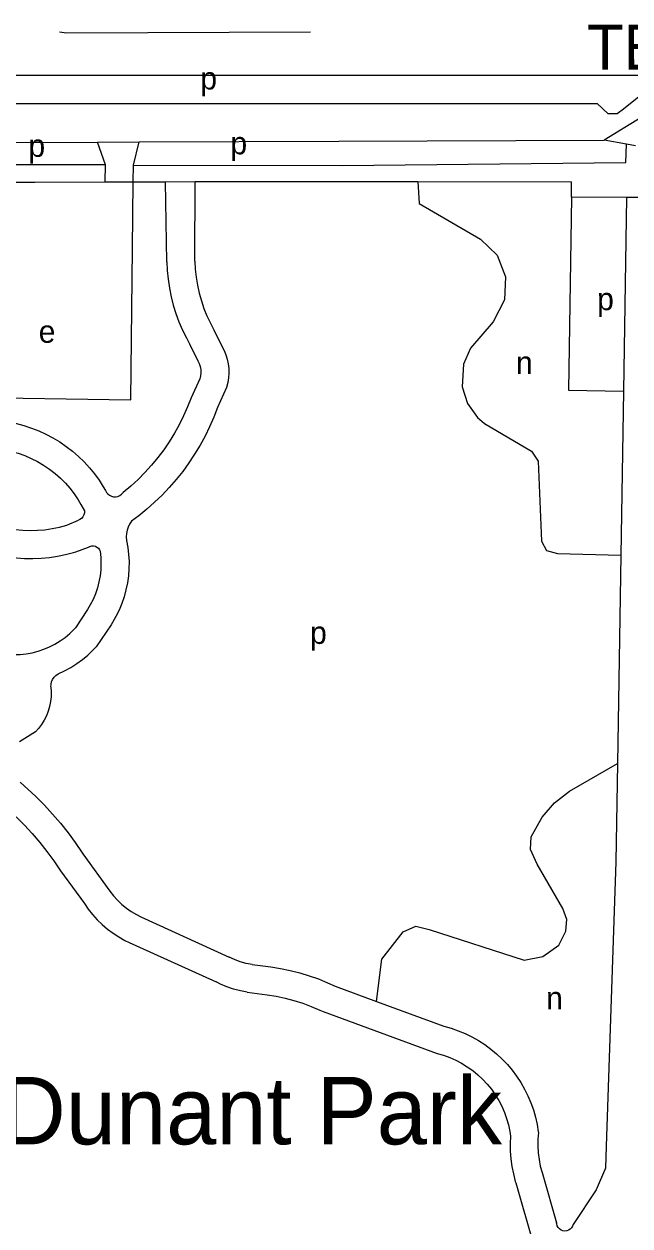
# Model space of a CAD drawing. Extents: x 159675 to 162108, y 386471 to 388472.
# Drawn here: x 160845.9 to 160953.7, y 388134.8 to 388348.5 of the extents above; entities that cross this region are included whole.
import ezdxf

# ---------------------------------------------------------------- set-up
doc = ezdxf.new("R2010")
doc.units = 0
for name, color, linetype in [('BLT_Basislijn', 7, 'Continuous'), ('BLT_Centroide', 7, 'Continuous'), ('BLT_Sport_parknaam', 7, 'Continuous'), ('BLT_Straatnaam_hoofdweg', 7, 'Continuous')]:
    doc.layers.add(name, color=color, linetype=linetype)

msp = doc.modelspace()

# ---------------------------------------------------------------- linework, layer by layer
at = {"layer": 'BLT_Basislijn'}
for p, q in [((160821.1, 388334.42), (160947.87, 388334.42)), ((160955.66, 388331.9), (160949.08, 388327.91)), ((160844.12, 388327.48), (160858.93, 388327.54)), ((160858.93, 388327.54), (160866.37, 388327.57)), ((160865.33, 388323.41), (160866.37, 388327.57)), ((160866.37, 388327.57), (160901.87, 388327.73)), ((160901.87, 388327.73), (160949.08, 388327.91)), ((160953.05, 388327.19), (160949.08, 388327.91)), ((160954.67, 388326.9), (160953.05, 388327.19)), ((160860.38, 388323.49), (160834.93, 388323.49)), ((160865.3, 388320.48), (160865.33, 388323.41)), ((160865.33, 388323.41), (160902.5, 388323.36)), ((160834.87, 388320.46), (160847.78, 388320.42)), ((160847.78, 388320.42), (160860.32, 388320.46)), ((160860.32, 388320.46), (160865.3, 388320.48)), ((160865.17, 388308.55), (160865.3, 388320.48)), ((160865.3, 388320.48), (160871.06, 388320.49)), ((160871.06, 388320.49), (160876.3, 388320.51)), ((160871.28, 388306.27), (160871.06, 388320.49)), ((160876.28, 388306.38), (160876.3, 388320.51)), ((160915.92, 388320.51), (160943.27, 388320.47)), ((160943.27, 388317.73), (160943.27, 388320.47)), ((160953.1, 388317.71), (160943.27, 388317.73)), ((160953.1, 388317.71), (160952.54, 388283.24)), ((160958.1, 388317.71), (160953.1, 388317.71)), ((160879.66, 388294.17), (160881.06, 388291.24)), ((160875.32, 388291.69), (160876.79, 388288.64)), ((160877.15, 388285.46), (160875.62, 388282.07)), ((160881.89, 388283.9), (160880.32, 388280.36)), ((160952.54, 388283.24), (160952.08, 388254.1)), ((160856.01, 388263.13), (160856.63, 388261.97)), ((160853.62, 388259.46), (160855.56, 388260.3)), ((160855.09, 388254.68), (160857.32, 388255.5)), ((160952.08, 388254.1), (160951.48, 388217.02)), ((160857.16, 388244.44), (160855.02, 388241.18)), ((160861.36, 388241.73), (160858.71, 388237.81)), ((160847.89, 388222.68), (160845.07, 388220.88)), ((160951.48, 388217.02), (160951.2, 388199.58)), ((160845.19, 388213.7), (160847.98, 388211.17)), ((160856.34, 388201), (160861.15, 388194.36)), ((160852.34, 388197.98), (160856.61, 388192.15)), ((160951.2, 388199.58), (160949.46, 388149.03)), ((160866.67, 388189.78), (160882.36, 388182.64)), ((160864.57, 388185.24), (160880.04, 388178.21)), ((160886.46, 388181.28), (160889.8, 388180.89)), ((160885.6, 388176.36), (160889.12, 388175.94)), ((160901.26, 388177.43), (160908.59, 388174.74)), ((160908.59, 388174.74), (160920.57, 388170.33)), ((160899.08, 388172.93), (160919.36, 388165.48)), ((160933.36, 388142.49), (160936.55, 388131.55)), ((160938.16, 388143.89), (160940.64, 388135.39)), ((160947.67, 388141.27), (160943.6, 388135.09))]:
    msp.add_line(p, q, dxfattribs=at)
for points in [[(160896.86, 388347.06), (160853.43, 388346.93), (160852.19, 388347.06)], [(160798.39, 388339.42), (160959.39, 388339.42)], [(160959.39, 388339.42), (160958.3, 388338.04), (160952.53, 388333.38), (160951.44, 388332.55), (160949.79, 388332.55), (160947.87, 388334.42)], [(160860.38, 388323.49), (160858.93, 388327.54)], [(160902.5, 388323.36), (160952.93, 388323.92), (160953.05, 388327.19)], [(160860.32, 388320.46), (160860.38, 388323.49)], [(160876.3, 388320.51), (160888.57, 388320.55), (160915.92, 388320.51)], [(160915.92, 388320.51), (160916.17, 388316.64), (160927.11, 388310.29), (160930.04, 388307.41), (160931.54, 388303.58), (160931.36, 388299.48), (160929.36, 388295.6), (160925.32, 388290.89), (160924.06, 388288.08), (160923.84, 388284), (160924.79, 388281.07), (160926.59, 388278.58), (160927.83, 388277.53), (160936.18, 388272.56), (160937.33, 388270.81), (160937.93, 388256.58), (160938.86, 388254.94), (160940.8, 388254.36), (160952.08, 388254.1)], [(160943.27, 388317.73), (160942.73, 388283.45), (160952.54, 388283.24)], [(160834.15, 388282.21), (160864.89, 388281.69), (160865.17, 388308.55)], [(160871.28, 388306.27), (160871.36, 388304.7), (160871.51, 388303.14), (160871.74, 388301.59), (160872.05, 388300.05), (160872.44, 388298.54), (160872.91, 388297.04), (160873.45, 388295.57), (160874.07, 388294.12), (160874.76, 388292.72), (160875.32, 388291.69)], [(160876.28, 388306.38), (160876.35, 388304.95), (160876.5, 388303.52), (160876.73, 388302.1), (160877.04, 388300.7), (160877.43, 388299.32), (160877.89, 388297.96), (160878.43, 388296.63), (160879.04, 388295.33), (160879.66, 388294.17)], [(160881.06, 388291.24), (160881.46, 388290.5), (160881.79, 388289.73), (160882.05, 388288.93), (160882.22, 388288.11), (160882.32, 388287.27), (160882.34, 388286.43), (160882.28, 388285.6), (160882.13, 388284.77), (160881.89, 388283.9)], [(160876.79, 388288.64), (160877.04, 388288.15), (160877.22, 388287.63), (160877.32, 388287.09), (160877.34, 388286.54), (160877.28, 388285.99), (160877.15, 388285.46)], [(160875.62, 388282.07), (160874.98, 388280.44), (160874.27, 388278.85), (160873.49, 388277.28), (160872.64, 388275.76), (160871.72, 388274.27), (160870.73, 388272.83), (160869.68, 388271.44), (160868.57, 388270.09), (160867.39, 388268.8), (160866.16, 388267.56), (160864.87, 388266.38), (160863.51, 388265.26)], [(160880.32, 388280.36), (160879.64, 388278.63), (160878.9, 388276.93), (160878.08, 388275.26), (160877.19, 388273.63), (160876.23, 388272.04), (160875.2, 388270.49), (160874.11, 388268.99), (160872.95, 388267.53), (160871.73, 388266.13), (160870.46, 388264.78), (160869.12, 388263.49), (160867.73, 388262.25), (160866.29, 388261.08), (160864.99, 388260.11)], [(160841.73, 388277.96), (160843.14, 388277.76), (160844.51, 388277.48), (160845.87, 388277.12), (160847.2, 388276.69), (160848.51, 388276.18), (160849.78, 388275.6), (160851.02, 388274.94), (160852.23, 388274.22), (160853.38, 388273.42), (160854.49, 388272.57), (160855.56, 388271.65), (160856.56, 388270.67), (160857.51, 388269.64), (160858.4, 388268.55), (160859.22, 388267.42), (160859.98, 388266.24), (160860.37, 388265.58)], [(160841.17, 388272.99), (160842.41, 388272.81), (160843.64, 388272.55), (160844.84, 388272.21), (160846.02, 388271.79), (160847.17, 388271.3), (160848.29, 388270.74), (160849.37, 388270.1), (160850.41, 388269.4), (160851.4, 388268.64), (160852.34, 388267.81), (160853.23, 388266.92), (160854.05, 388265.98), (160854.82, 388264.99), (160855.52, 388263.95), (160856.01, 388263.13)], [(160830.61, 388266.38), (160833.51, 388263.3), (160834.57, 388262.5), (160835.67, 388261.77), (160836.82, 388261.11), (160838, 388260.52), (160839.21, 388260), (160840.46, 388259.55), (160841.73, 388259.18), (160843.02, 388258.89), (160844.32, 388258.68), (160845.64, 388258.55), (160846.96, 388258.49), (160848.28, 388258.52), (160849.6, 388258.62), (160850.91, 388258.81), (160852.21, 388259.07), (160853.48, 388259.42), (160853.62, 388259.46)], [(160825.85, 388264.04), (160826.77, 388262.9), (160827.76, 388261.81), (160828.8, 388260.78), (160829.89, 388259.8), (160831.04, 388258.89), (160832.23, 388258.04), (160833.47, 388257.26), (160834.75, 388256.54), (160836.07, 388255.9), (160837.42, 388255.33), (160838.8, 388254.84), (160840.21, 388254.42), (160841.63, 388254.07), (160843.07, 388253.81), (160844.53, 388253.62), (160845.99, 388253.52), (160847.45, 388253.49), (160848.92, 388253.55), (160850.38, 388253.68), (160851.83, 388253.89), (160853.27, 388254.19), (160854.68, 388254.56), (160855.09, 388254.68)], [(160860.37, 388265.58), (160860.54, 388265.25), (160860.79, 388264.97), (160861.09, 388264.74), (160861.44, 388264.57), (160861.81, 388264.49), (160862.18, 388264.48), (160862.56, 388264.55), (160862.91, 388264.7), (160863.22, 388264.92), (160863.51, 388265.26)], [(160856.63, 388261.97), (160856.61, 388261.6), (160856.51, 388261.24), (160856.33, 388260.92), (160856.09, 388260.64), (160855.8, 388260.41), (160855.56, 388260.3)], [(160864.99, 388260.11), (160864.66, 388259.61), (160864.4, 388259.08), (160864.21, 388258.52), (160864.1, 388257.94), (160864.07, 388257.35), (160864.13, 388256.7)], [(160857.32, 388255.5), (160857.61, 388255.66), (160857.93, 388255.74), (160858.25, 388255.75), (160858.57, 388255.67), (160858.86, 388255.52), (160859.11, 388255.31), (160859.3, 388255.04), (160859.4, 388254.78)], [(160864.13, 388256.7), (160864.35, 388255.46), (160864.49, 388254.2), (160864.56, 388252.94), (160864.54, 388251.67), (160864.44, 388250.41), (160864.27, 388249.16), (160864.01, 388247.92), (160863.68, 388246.7), (160863.27, 388245.51), (160862.78, 388244.34), (160862.23, 388243.2), (160861.6, 388242.1), (160861.36, 388241.73)], [(160859.4, 388254.78), (160859.52, 388253.69), (160859.56, 388252.6), (160859.52, 388251.51), (160859.4, 388250.42), (160859.21, 388249.34), (160858.93, 388248.28), (160858.58, 388247.24), (160858.15, 388246.23), (160857.65, 388245.26), (160857.16, 388244.44)], [(160841.96, 388236.59), (160843.04, 388236.46), (160844.12, 388236.41), (160845.2, 388236.45), (160846.27, 388236.56), (160847.34, 388236.75), (160848.39, 388237.02), (160849.41, 388237.36), (160850.4, 388237.79), (160851.37, 388238.28), (160852.29, 388238.84), (160853.17, 388239.47), (160854, 388240.17), (160854.77, 388240.92), (160855.02, 388241.18)], [(160851.95, 388233), (160853.09, 388233.53), (160854.19, 388234.13), (160855.25, 388234.8), (160856.26, 388235.54), (160857.22, 388236.34), (160858.13, 388237.2), (160858.71, 388237.81)], [(160850.66, 388230.69), (160850.68, 388231.14), (160850.79, 388231.58), (160850.96, 388232), (160851.21, 388232.37), (160851.52, 388232.7), (160851.95, 388233)], [(160850.66, 388230.69), (160850.72, 388229.81), (160850.71, 388228.93), (160850.61, 388228.05), (160850.43, 388227.18), (160850.18, 388226.33), (160849.85, 388225.51), (160849.45, 388224.73), (160848.98, 388223.98), (160848.44, 388223.27), (160847.89, 388222.68)], [(160908.59, 388174.74), (160909.52, 388182.26), (160913.35, 388187.14), (160915.61, 388188.1), (160917.99, 388187.56), (160934.89, 388182.09), (160938.18, 388182.72), (160941.01, 388184.72), (160942.25, 388187.21), (160942.46, 388189.3), (160941.73, 388191.26), (160937.19, 388199.16), (160936.02, 388201.74), (160936.14, 388204.02), (160938.05, 388207.49), (160940.27, 388210.04), (160942.95, 388212.11), (160951.48, 388217.02)], [(160847.98, 388211.17), (160849.5, 388209.64), (160850.97, 388208.05), (160852.37, 388206.41), (160853.72, 388204.72), (160855, 388202.98), (160856.21, 388201.19), (160856.34, 388201)], [(160844.5, 388207.58), (160845.95, 388206.11), (160847.35, 388204.59), (160848.69, 388203.02), (160849.96, 388201.39), (160851.18, 388199.72), (160852.34, 388197.98)], [(160861.15, 388194.36), (160861.79, 388193.52), (160862.5, 388192.73), (160863.27, 388192), (160864.09, 388191.33), (160864.96, 388190.72), (160865.87, 388190.18), (160866.67, 388189.78)], [(160856.61, 388192.15), (160857.31, 388191.13), (160858.08, 388190.17), (160858.91, 388189.26), (160859.8, 388188.4), (160860.74, 388187.6), (160861.73, 388186.87), (160862.76, 388186.2), (160863.84, 388185.6), (160864.57, 388185.24)], [(160886.46, 388181.28), (160885.4, 388181.51), (160884.36, 388181.81), (160883.34, 388182.19), (160882.36, 388182.64)], [(160889.8, 388180.89), (160891.53, 388180.61), (160893.24, 388180.26), (160894.93, 388179.83), (160896.61, 388179.31), (160898.26, 388178.73), (160899.88, 388178.07), (160901.26, 388177.43)], [(160885.6, 388176.36), (160884.37, 388176.61), (160883.16, 388176.94), (160881.97, 388177.35), (160880.82, 388177.84), (160880.04, 388178.21)], [(160889.12, 388175.94), (160890.73, 388175.68), (160892.33, 388175.34), (160893.9, 388174.92), (160895.46, 388174.43), (160896.99, 388173.86), (160898.48, 388173.21), (160899.08, 388172.93)], [(160920.57, 388170.33), (160921.86, 388169.97), (160923.12, 388169.54), (160924.36, 388169.02), (160925.56, 388168.44), (160926.73, 388167.78), (160927.85, 388167.06), (160928.93, 388166.27), (160929.96, 388165.42), (160930.94, 388164.5), (160931.87, 388163.53), (160932.73, 388162.51), (160933.53, 388161.44), (160934.26, 388160.32), (160934.93, 388159.16), (160935.52, 388157.96), (160936.05, 388156.73), (160936.5, 388155.47), (160936.87, 388154.18), (160937.16, 388152.88), (160937.38, 388151.56), (160937.39, 388151.45)], [(160919.36, 388165.48), (160920.5, 388165.16), (160921.61, 388164.76), (160922.69, 388164.29), (160923.74, 388163.74), (160924.74, 388163.13), (160925.71, 388162.45), (160926.62, 388161.7), (160927.48, 388160.9), (160928.29, 388160.03), (160929.03, 388159.12), (160929.71, 388158.16), (160930.33, 388157.15), (160930.87, 388156.1), (160931.35, 388155.02), (160931.74, 388153.91), (160932.07, 388152.78), (160932.31, 388151.62), (160932.43, 388150.81)], [(160932.43, 388150.81), (160932.38, 388149.45), (160932.4, 388148.1), (160932.51, 388146.74), (160932.69, 388145.39), (160932.95, 388144.06), (160933.29, 388142.74), (160933.36, 388142.49)], [(160937.39, 388151.45), (160937.3, 388150.25), (160937.29, 388149.04), (160937.36, 388147.84), (160937.51, 388146.64), (160937.74, 388145.46), (160938.04, 388144.3), (160938.16, 388143.89)], [(160949.46, 388149.03), (160949.35, 388145.12), (160947.67, 388141.27)], [(160943.6, 388135.09), (160943.49, 388134.77), (160943.31, 388134.47), (160943.07, 388134.23), (160942.77, 388134.05), (160942.45, 388133.94), (160942.1, 388133.91), (160941.76, 388133.96), (160941.44, 388134.08), (160941.15, 388134.28), (160940.92, 388134.54), (160940.76, 388134.84), (160940.66, 388135.17), (160940.64, 388135.39)]]:
    msp.add_lwpolyline(points, dxfattribs=at)

# ---------------------------------------------------------------- texts
at = {"layer": 'BLT_Centroide'}
for s, p in [('p', (160877.24, 388336.9)), ('p', (160882.6, 388325.37)), ('p', (160846.66, 388324.92)), ('p', (160947.85, 388297.65)), ('e', (160848.49, 388291.86)), ('n', (160933.41, 388286.33)), ('p', (160896.77, 388238.32)), ('n', (160938.77, 388173.35))]:
    msp.add_text(s, height=4, dxfattribs=at).set_placement(p)
at = {"layer": 'BLT_Sport_parknaam'}
msp.add_text('Henri Dunant Park', height=12, dxfattribs=at).set_placement((160798.92, 388149.33))
at = {"layer": 'BLT_Straatnaam_hoofdweg'}
msp.add_text('TEMPELLAAN', height=8, rotation=0.0942, dxfattribs=at).set_placement((160946.03, 388340.42))

doc.saveas('drawing.dxf')
